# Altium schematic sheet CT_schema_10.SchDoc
size 274 x 160 mm
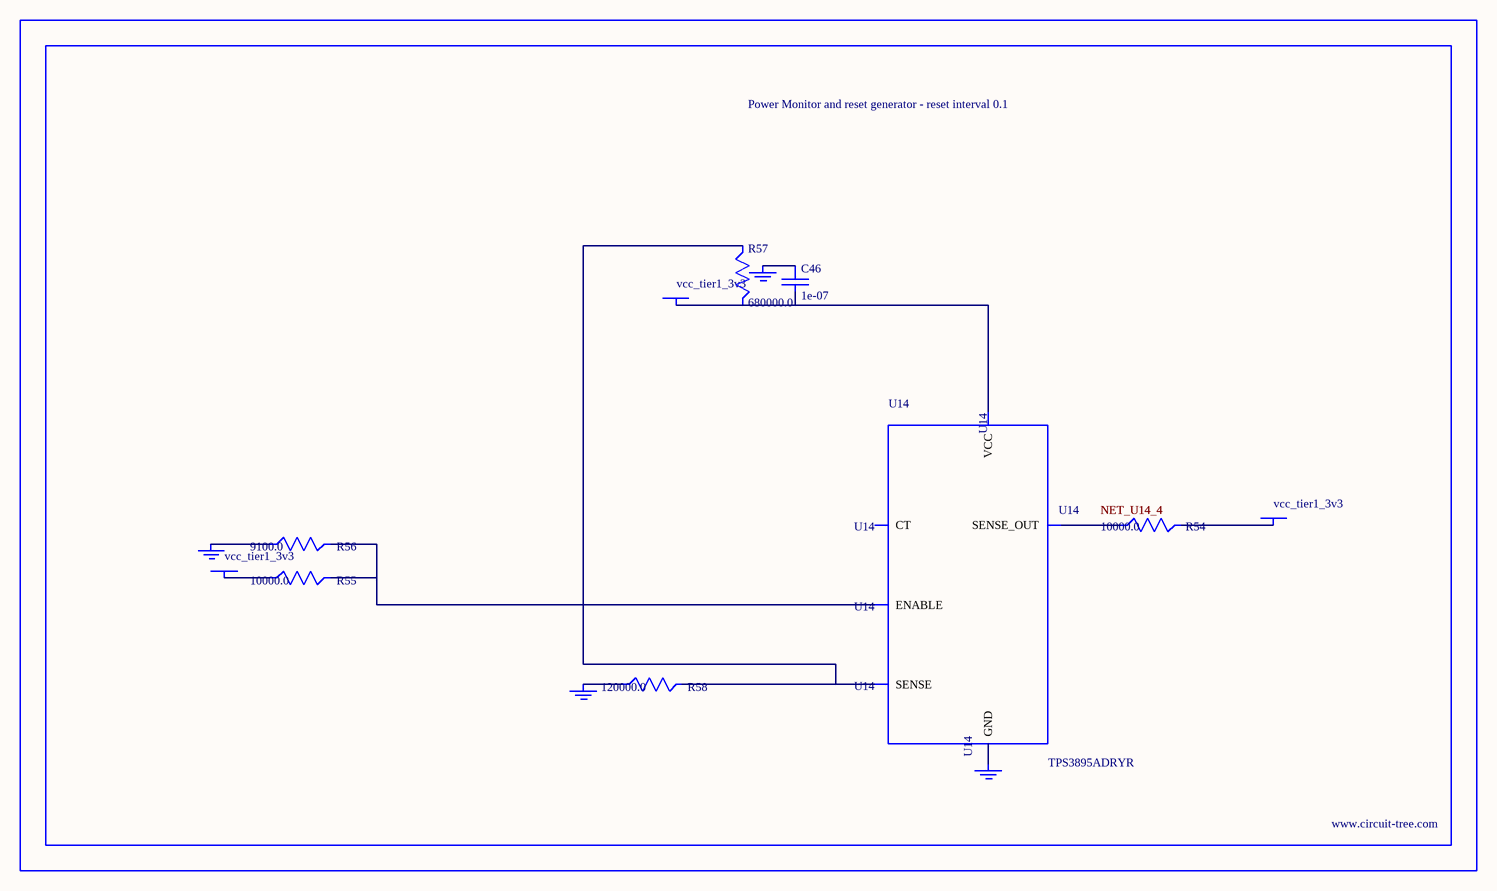
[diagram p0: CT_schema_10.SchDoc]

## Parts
BORDER9  (no value)
C46  1e-07  [C0402]
GND_INSTANCE_9_0  (no value)
GND_INSTANCE_9_1  (no value)
GND_INSTANCE_9_2  (no value)
GND_INSTANCE_9_3  (no value)
POWER_INSTANCE_9_0  vcc_tier1_3v3
POWER_INSTANCE_9_1  vcc_tier1_3v3
POWER_INSTANCE_9_2  vcc_tier1_3v3
R54  10000.0  [R0603]
R55  10000.0  [R0603]
R56  9100.0  [R0603]
R57  680000.0  [R0603]
R58  120000.0  [R0603]
U14  TPS3895ADRYR  [SON-6]

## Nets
NetC46_1: C46.1 GND_INSTANCE_9_2.0(GND)
NetC46_2: C46.2 POWER_INSTANCE_9_2.0(PWR) R57.2 U14.6(VCC)
NetGND_INSTANCE_9_0_0: GND_INSTANCE_9_0.0(GND) R56.1
NetGND_INSTANCE_9_1_0: GND_INSTANCE_9_1.0(GND) R58.1
NetGND_INSTANCE_9_3_0: GND_INSTANCE_9_3.0(GND) U14.2(GND)
NetPOWER_INSTANCE_9_0_0: POWER_INSTANCE_9_0.0(PWR) R55.1
NetPOWER_INSTANCE_9_1_0: POWER_INSTANCE_9_1.0(PWR) R54.2
NetR54_1: R54.1 U14.4(SENSE_OUT)
NetR55_2: R55.2 R56.2 U14.1(ENABLE)
NetR57_1: R57.1 R58.2 U14.3(SENSE)

Not connected (* = marked no-connect by the designer): U14 5(CT)

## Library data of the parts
BORDER9 = BORDER_PAGE9
C46 = C0402C104K3RACTU
GND_INSTANCE_9_0-GND_INSTANCE_9_3 = GND
POWER_INSTANCE_9_0-POWER_INSTANCE_9_2 = PWR
R54 R55 = RC0603JR-0710KL
R56 = RC0603JR-079K1L
R57 = RC0603JR-07680KL
R58 = RC0603JR-07120KL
